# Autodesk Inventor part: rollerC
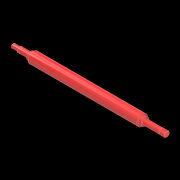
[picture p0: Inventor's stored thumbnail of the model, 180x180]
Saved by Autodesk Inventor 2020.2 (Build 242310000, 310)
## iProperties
Manager: PART
Category: 12
Company: 15
Created: 2020-10
Part Number: rollerC
Material: Generic
Document SubType Name: Modeling
Designer: Apardo
Density: 1 g/cm^3
Appearance: Light Red
Project: PLATE ROLLING MACHINE
Cost Center: 1
Description: ROLLER C
Engineer: STEEL C45
Vendor: 12
Stock Number: 1.11
Authority: D. JAEGER
Engr Approved By: D. JAEGER
Author: Apardo
Revision Number: 1.0
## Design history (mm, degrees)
sketch "Sketch1"
  geometry: L1 (0, 0)-(-263.363, 0); L2 (-212, 0)-(-212, 6); L3 (-156, 11)-(-156, 15); L4 (-156, 15)-(144, 15); L5 (144, 15)-(144, 11); L6 (144, 11)-(152, 11); L7 (152, 11)-(152, 7.5); L8 (212, 7.5)-(212, 0); L9 (212, 0)-(-212, 0); L10 (152, 7.5)-(212, 7.5); L11 (-212, 6)-(-194, 6); L12 (-194, 6)-(-194, 7.5); L13 (-194, 7.5)-(-164, 7.5); L14 (-164, 7.5)-(-164, 11); L15 (-164, 11)-(-156, 11); 1 further point
  constraints: 30 end point, 9 perpendicular, 2 horizontal, 2 vertical, 1 point on line
  dimensions: "d0" = 424 distance of L8.end L2.start; "d1" = 212 distance from line of L1.start L2 (= 0.5 x d0); "d2" = 30 diameter of L4 L1; "d4" = 22 diameter of L6 L1; "d6" = 68 distance from line of L5 L8.end; "d11" = 15 diameter of L10 L1; "d13" = 60 distance between parallel lines of L7 L8; "d14" = 12 diameter of L11 L1; "d15" = 15 diameter of L13 L1; "d16" = 22 diameter of L15 L1; "d17" = 56 distance between parallel lines of L3 L2; "d18" = 48 distance between parallel lines of L2 L14; "d19" = 18 distance of L2.end L11.end
revolve "Revolution1" sketch "Sketch1" stored, may be unused: angle "d7" = 90 deg
chamfer "Chamfer1" distance "d8" = 1; stored, may be unused: second distance "d9" = 2, angle "d10" = 45 deg
workplane "Work Plane1"
sketch "Sketch2"
  geometry: L1 (209, 0)-(194, 0); L2 (207, 2)-(196, 2); L3 (196, -2)-(207, -2); L4 (212, 6)-(212, -6) reference; A1 r 2 centre (207, 0) between (207, -2) and (207, 2); A2 r 2 centre (196, 0) between (196, 2) and (196, -2); 4 further points
  constraints: 8 end point, 7 point on circle, 4 tangent, 2 centre point, 2 midpoint, 2 point on line, 1 horizontal, 1 horizontal alignment, 1 parallel
  dimensions: "d21" = 3 distance from line of L4 L1.start; "d22" = 15 distance of L1.start L1.end; "d23" = 2 radius of A2
extrude "Extrusion1" cut sketch "Sketch2" distance "d24" = 4.503; taper "d25" = 0 deg
sketch "Sketch3"
  geometry: L1 (-6, -6)-(6, -6); L2 (6, -6)-(6, 6); L3 (6, 6)-(-6, 6); L4 (-6, 6)-(-6, -6); L5 (-6, -6)-(6, 6); L6 (6, -6)-(-6, 6); C1 r 10 at (0, 0); 1 further point
  constraints: 12 end point, 2 midpoint, 2 parallel, 2 perpendicular, 1 centre point, 1 coincident, 1 horizontal
  dimensions: "d26" = 12 distance of L2.end L3.end
extrude "Extrusion2" cut sketch "Sketch3" distance "d27" = 15; taper "d28" = 0 deg
body "Solid1"
other parameters: "d20" = 8
